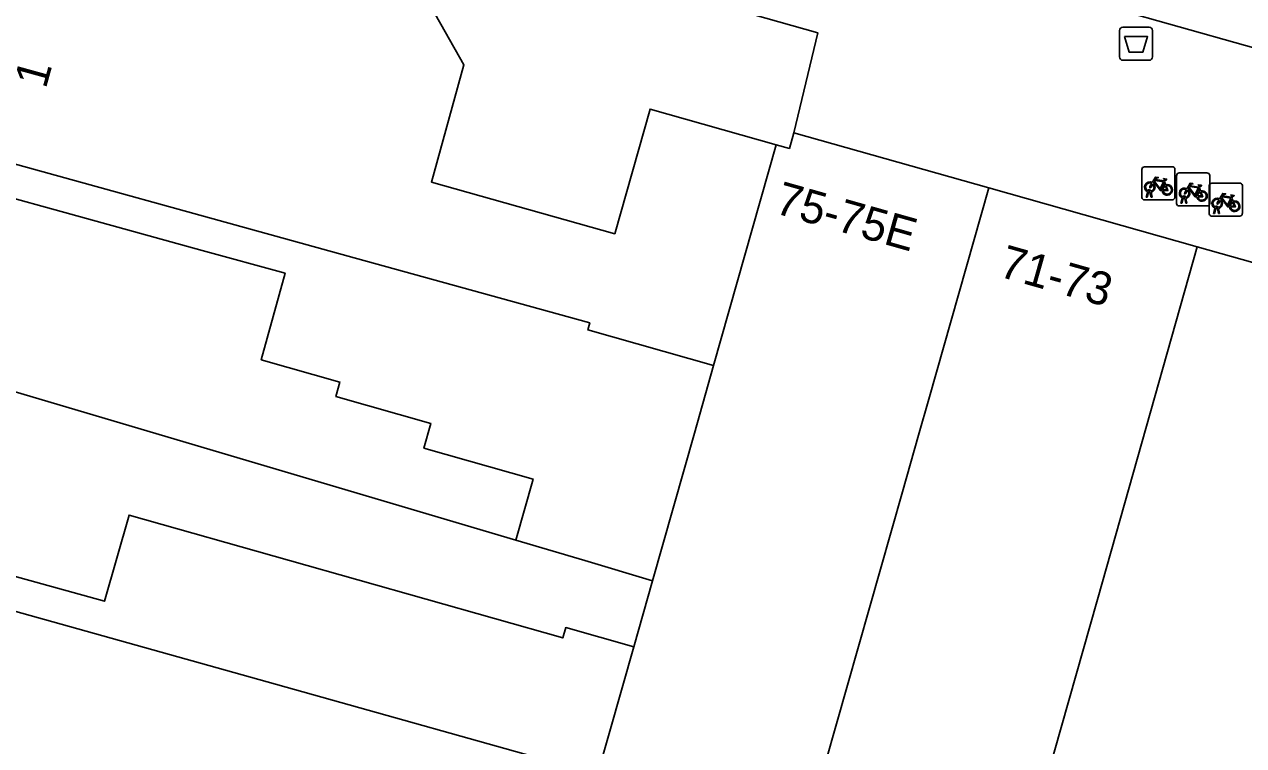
# Model space of a CAD drawing. Extents: x 158086 to 159499, y 382904 to 383981.
# Drawn here: x 158729.8 to 158766.64, y 383287.22 to 383309.02 of the extents above; entities that cross this region are included whole.
import ezdxf

# ---------------------------------------------------------------- set-up
doc = ezdxf.new("R2010")
doc.units = 0
for name, color, linetype in [('IMGEO_Afvalbak', 7, 'Continuous'), ('IMGEO_Erf', 7, 'Continuous'), ('IMGEO_Fietsenrek', 7, 'Continuous'), ('IMGEO_Pand', 7, 'Continuous'), ('IMGEO_Pand_nummerreeks', 7, 'Continuous'), ('IMGEO_Parkeervlak_open', 7, 'Continuous'), ('IMGEO_Voetpad_open', 7, 'Continuous')]:
    doc.layers.add(name, color=color, linetype=linetype)

msp = doc.modelspace()

# ---------------------------------------------------------------- linework, layer by layer
at = {"layer": 'IMGEO_Afvalbak'}
for p, q in [((158762.893, 383308.038), (158762.893, 383308.838)), ((158762.893, 383308.838), (158762.893, 383308.038)), ((158762.993, 383308.938), (158763.783, 383308.938)), ((158763.783, 383308.938), (158762.993, 383308.938)), ((158763.883, 383308.838), (158763.883, 383308.038)), ((158763.883, 383308.038), (158763.883, 383308.838)), ((158763.783, 383307.938), (158762.993, 383307.938)), ((158762.993, 383307.938), (158763.783, 383307.938))]:
    msp.add_line(p, q, dxfattribs=at)
msp.add_lwpolyline([(158763.036, 383308.652), (158763.74, 383308.652), (158763.591, 383308.182), (158763.185, 383308.182), (158763.036, 383308.652)], dxfattribs=at)
for centre, start, end in [((158762.993, 383308.838), 90, 180), ((158762.993, 383308.838), 90, 180), ((158763.783, 383308.838), 0, 90), ((158763.783, 383308.838), 360, 90), ((158762.993, 383308.038), 180, 270), ((158762.993, 383308.038), 180, 270), ((158763.783, 383308.038), 270, 0), ((158763.783, 383308.038), 270, 0)]:
    msp.add_arc(centre, 0.1, start, end, dxfattribs=at)
at = {"layer": 'IMGEO_Erf'}
for points in [[(158750.621, 383298.706), (158746.826, 383299.786), (158746.884, 383299.995), (158740.051, 383301.883), (158726.638, 383305.589), (158726.38, 383304.619), (158731.2, 383303.287), (158735.174, 383302.189), (158737.677, 383301.497), (158736.955, 383298.883), (158739.334, 383298.209), (158739.21, 383297.772), (158742.082, 383296.958), (158741.87, 383296.21), (158745.171, 383295.274), (158744.648, 383293.427), (158746.73, 383292.809), (158748.777, 383292.201), (158750.043, 383296.667)], [(158723.419, 383294.014), (158723.139, 383293.069), (158727.954, 383291.719), (158737.135, 383289.145), (158747.117, 383286.346), (158748.21, 383290.202), (158746.156, 383290.784), (158746.068, 383290.474), (158737.806, 383292.815), (158732.961, 383294.188), (158732.222, 383291.582), (158728.239, 383292.682)]]:
    msp.add_lwpolyline(points, close=True, dxfattribs=at)
at = {"layer": 'IMGEO_Fietsenrek'}
for p, q in [((158763.565, 383303.793), (158763.565, 383304.634)), ((158763.565, 383304.634), (158763.565, 383303.793)), ((158763.64, 383304.718), (158764.481, 383304.718)), ((158764.481, 383304.718), (158763.64, 383304.718)), ((158764.565, 383304.643), (158764.565, 383303.802)), ((158764.565, 383303.802), (158764.565, 383304.643)), ((158764.252, 383304.267), (158764.288, 383304.172)), ((158764.616, 383303.607), (158764.616, 383304.448)), ((158764.616, 383304.448), (158764.616, 383303.607)), ((158764.691, 383304.532), (158765.532, 383304.532)), ((158765.532, 383304.532), (158764.691, 383304.532)), ((158765.616, 383304.457), (158765.616, 383303.616)), ((158765.616, 383303.616), (158765.616, 383304.457)), ((158763.692, 383303.802), (158763.731, 383303.962)), ((158763.761, 383303.95), (158763.726, 383303.802)), ((158763.803, 383303.974), (158763.802, 383303.978)), ((158763.844, 383303.802), (158763.81, 383303.944)), ((158763.834, 383303.985), (158763.835, 383303.978)), ((158763.842, 383303.948), (158763.877, 383303.802)), ((158765.303, 383304.081), (158765.339, 383303.986)), ((158765.601, 383303.299), (158765.601, 383304.14)), ((158765.601, 383304.14), (158765.601, 383303.299)), ((158765.676, 383304.224), (158766.517, 383304.224)), ((158766.517, 383304.224), (158765.676, 383304.224)), ((158766.601, 383304.149), (158766.601, 383303.308)), ((158766.601, 383303.308), (158766.601, 383304.149)), ((158764.49, 383303.718), (158763.649, 383303.718)), ((158763.649, 383303.718), (158764.49, 383303.718)), ((158763.726, 383303.802), (158763.692, 383303.802)), ((158763.877, 383303.802), (158763.844, 383303.802)), ((158765.541, 383303.532), (158764.7, 383303.532)), ((158764.7, 383303.532), (158765.541, 383303.532)), ((158764.743, 383303.616), (158764.782, 383303.776)), ((158764.777, 383303.616), (158764.743, 383303.616)), ((158764.812, 383303.764), (158764.777, 383303.616)), ((158764.854, 383303.788), (158764.853, 383303.792)), ((158764.895, 383303.616), (158764.861, 383303.758)), ((158764.885, 383303.799), (158764.886, 383303.792)), ((158764.893, 383303.762), (158764.928, 383303.616)), ((158764.928, 383303.616), (158764.895, 383303.616)), ((158766.288, 383303.773), (158766.324, 383303.678)), ((158766.526, 383303.224), (158765.685, 383303.224)), ((158765.685, 383303.224), (158766.526, 383303.224)), ((158765.728, 383303.308), (158765.767, 383303.468)), ((158765.762, 383303.308), (158765.728, 383303.308)), ((158765.797, 383303.456), (158765.762, 383303.308)), ((158765.839, 383303.48), (158765.838, 383303.484)), ((158765.88, 383303.308), (158765.846, 383303.45)), ((158765.87, 383303.491), (158765.871, 383303.484)), ((158765.878, 383303.454), (158765.913, 383303.308)), ((158765.913, 383303.308), (158765.88, 383303.308))]:
    msp.add_line(p, q, dxfattribs=at)
for points in [[(158763.878, 383304.244), (158763.973, 383304.408), (158764.059, 383304.394), (158764.061, 383304.385), (158764.005, 383304.374), (158763.978, 383304.329), (158764.234, 383304.288)], [(158764.174, 383304), (158764.124, 383304), (158763.933, 383304.251), (158763.914, 383304.219)], [(158764.221, 383304.263), (158763.964, 383304.304), (158763.947, 383304.275), (158764.114, 383304.055), (158764.221, 383304.263)], [(158764.269, 383304.165), (158764.239, 383304.242), (158764.13, 383304.024), (158764.173, 383304.024)], [(158764.234, 383304.288), (158764.259, 383304.337), (158764.253, 383304.341), (158764.23, 383304.345), (158764.218, 383304.352), (158764.217, 383304.355), (158764.219, 383304.36), (158764.314, 383304.345), (158764.316, 383304.335), (158764.306, 383304.322), (158764.294, 383304.316), (158764.28, 383304.322), (158764.252, 383304.267)], [(158763.899, 383304.192), (158763.847, 383304.102), (158763.807, 383304.077), (158763.808, 383304.124), (158763.863, 383304.218)], [(158764.203, 383304.024), (158764.323, 383304.023), (158764.279, 383304.137)], [(158764.299, 383304.144), (158764.354, 383303.999), (158764.204, 383303.999)], [(158764.95, 383304.006), (158764.898, 383303.916), (158764.858, 383303.891), (158764.859, 383303.938), (158764.914, 383304.032)], [(158764.929, 383304.058), (158765.024, 383304.222), (158765.11, 383304.208), (158765.112, 383304.199), (158765.056, 383304.188), (158765.029, 383304.143), (158765.285, 383304.102)], [(158765.225, 383303.814), (158765.175, 383303.814), (158764.984, 383304.065), (158764.965, 383304.033)], [(158765.272, 383304.077), (158765.015, 383304.118), (158764.998, 383304.089), (158765.165, 383303.869), (158765.272, 383304.077)], [(158765.32, 383303.979), (158765.29, 383304.056), (158765.181, 383303.838), (158765.224, 383303.838)], [(158765.254, 383303.838), (158765.374, 383303.837), (158765.33, 383303.951)], [(158765.35, 383303.958), (158765.405, 383303.813), (158765.255, 383303.813)], [(158765.285, 383304.102), (158765.31, 383304.151), (158765.304, 383304.155), (158765.281, 383304.159), (158765.269, 383304.166), (158765.268, 383304.169), (158765.27, 383304.174), (158765.365, 383304.159), (158765.367, 383304.149), (158765.357, 383304.136), (158765.345, 383304.13), (158765.331, 383304.136), (158765.303, 383304.081)], [(158765.914, 383303.75), (158766.009, 383303.914), (158766.095, 383303.9), (158766.097, 383303.891), (158766.041, 383303.88), (158766.014, 383303.835), (158766.27, 383303.794)], [(158765.935, 383303.698), (158765.883, 383303.608), (158765.843, 383303.583), (158765.844, 383303.63), (158765.899, 383303.724)], [(158766.21, 383303.506), (158766.16, 383303.506), (158765.969, 383303.757), (158765.95, 383303.725)], [(158766.257, 383303.769), (158766, 383303.81), (158765.983, 383303.781), (158766.15, 383303.561), (158766.257, 383303.769)], [(158766.305, 383303.671), (158766.275, 383303.748), (158766.166, 383303.53), (158766.209, 383303.53)], [(158766.239, 383303.53), (158766.359, 383303.529), (158766.315, 383303.643)], [(158766.335, 383303.65), (158766.39, 383303.505), (158766.24, 383303.505)], [(158766.27, 383303.794), (158766.295, 383303.843), (158766.289, 383303.847), (158766.266, 383303.851), (158766.254, 383303.858), (158766.253, 383303.861), (158766.255, 383303.866), (158766.35, 383303.851), (158766.352, 383303.841), (158766.342, 383303.828), (158766.33, 383303.822), (158766.316, 383303.828), (158766.288, 383303.773)]]:
    msp.add_lwpolyline(points, dxfattribs=at)
for centre, radius, start, end in [((158763.643, 383304.64), 0.0779, 92.4484, 184.2845), ((158763.643, 383304.64), 0.0779, 92.4484, 184.2845), ((158764.487, 383304.64), 0.0779, 2.4484, 94.2845), ((158764.487, 383304.64), 0.0779, 2.4484, 94.2845), ((158763.805, 383304.103), 0.159, 62.6766, 242.1369), ((158764.694, 383304.454), 0.0779, 92.4484, 184.2845), ((158764.694, 383304.454), 0.0779, 92.4484, 184.2845), ((158765.538, 383304.454), 0.0779, 2.4484, 94.2845), ((158765.538, 383304.454), 0.0779, 2.4484, 94.2845), ((158763.805, 383304.103), 0.129, 63.3192, 238.903), ((158763.785, 383303.974), 0.0499, 12.8025, 158.6934), ((158763.805, 383304.103), 0.159, 253.9967, 271.7867), ((158763.785, 383303.974), 0.0174, 12.8025, 163.4502), ((158763.805, 383304.103), 0.129, 253.415, 269.0204), ((158763.805, 383304.103), 0.129, 283.6043, 43.4302), ((158763.805, 383304.103), 0.159, 283.5766, 46.6042), ((158764.332, 383304.019), 0.159, 113.3408, 178.3217), ((158764.332, 383304.019), 0.159, 187.0065, 105.7708), ((158764.332, 383304.019), 0.129, 113.923, 177.9556), ((158764.332, 383304.019), 0.129, 188.6715, 104.5883), ((158764.856, 383303.917), 0.159, 62.6766, 242.1369), ((158764.856, 383303.917), 0.129, 63.3192, 238.903), ((158764.856, 383303.917), 0.129, 283.6043, 43.4302), ((158764.856, 383303.917), 0.159, 283.5766, 46.6042), ((158765.383, 383303.833), 0.159, 113.3408, 178.3217), ((158765.383, 383303.833), 0.159, 187.0065, 105.7708), ((158765.383, 383303.833), 0.129, 113.923, 177.9556), ((158765.383, 383303.833), 0.129, 188.6715, 104.5883), ((158765.679, 383304.146), 0.0779, 92.4484, 184.2845), ((158765.679, 383304.146), 0.0779, 92.4484, 184.2845), ((158766.523, 383304.146), 0.0779, 2.4484, 94.2845), ((158766.523, 383304.146), 0.0779, 2.4484, 94.2845), ((158763.643, 383303.796), 0.0779, 182.4484, 274.2845), ((158763.643, 383303.796), 0.0779, 182.4484, 274.2845), ((158764.487, 383303.796), 0.0779, 272.4484, 4.2845), ((158764.487, 383303.796), 0.0779, 272.4484, 4.2845), ((158764.694, 383303.61), 0.0779, 182.4484, 274.2845), ((158764.694, 383303.61), 0.0779, 182.4484, 274.2845), ((158764.836, 383303.788), 0.0499, 12.8025, 158.6934), ((158764.856, 383303.917), 0.159, 253.9967, 271.7867), ((158764.836, 383303.788), 0.0174, 12.8025, 163.4502), ((158764.856, 383303.917), 0.129, 253.415, 269.0204), ((158765.538, 383303.61), 0.0779, 272.4484, 4.2845), ((158765.538, 383303.61), 0.0779, 272.4484, 4.2845), ((158765.841, 383303.609), 0.159, 62.6766, 242.1369), ((158765.841, 383303.609), 0.129, 63.3192, 238.903), ((158765.821, 383303.48), 0.0499, 12.8025, 158.6934), ((158765.841, 383303.609), 0.129, 283.6043, 43.4302), ((158765.841, 383303.609), 0.159, 283.5766, 46.6042), ((158766.368, 383303.525), 0.159, 113.3408, 178.3217), ((158766.368, 383303.525), 0.159, 187.0065, 105.7708), ((158766.368, 383303.525), 0.129, 113.923, 177.9556), ((158766.368, 383303.525), 0.129, 188.6715, 104.5883), ((158765.679, 383303.302), 0.0779, 182.4484, 274.2845), ((158765.679, 383303.302), 0.0779, 182.4484, 274.2845), ((158765.841, 383303.609), 0.159, 253.9967, 271.7867), ((158765.821, 383303.48), 0.0174, 12.8025, 163.4502), ((158765.841, 383303.609), 0.129, 253.415, 269.0204), ((158766.523, 383303.302), 0.0779, 272.4484, 4.2845), ((158766.523, 383303.302), 0.0779, 272.4484, 4.2845)]:
    msp.add_arc(centre, radius, start, end, dxfattribs=at)
at = {"layer": 'IMGEO_Pand'}
for points in [[(158734.063, 383310.168), (158729.552, 383311.413), (158728.013, 383310.572), (158726.638, 383305.589), (158740.051, 383301.883), (158746.884, 383299.995), (158746.826, 383299.786), (158750.621, 383298.706), (158752.515, 383305.385), (158748.706, 383306.463), (158747.639, 383302.691), (158742.1, 383304.249), (158743.079, 383307.796), (158742.083, 383309.564), (158738.149, 383310.65), (158736.503, 383309.495), (158734.326, 383310.095)], [(158756.328, 383294.885), (158756.815, 383296.607), (158757.123, 383297.693), (158758.936, 383304.084), (158753.051, 383305.749), (158752.916, 383305.271), (158752.515, 383305.385), (158750.621, 383298.706), (158750.043, 383296.667), (158748.777, 383292.201), (158748.21, 383290.202), (158747.117, 383286.346), (158745.223, 383279.663), (158745.391, 383279.615), (158745.532, 383279.575), (158748.385, 383278.764), (158751.259, 383277.947), (158751.502, 383277.878), (158751.64, 383278.365), (158751.727, 383278.671), (158752.016, 383279.689)], [(158726.38, 383304.619), (158724.891, 383299.284), (158744.648, 383293.427), (158745.171, 383295.274), (158741.87, 383296.21), (158742.082, 383296.958), (158739.21, 383297.772), (158739.334, 383298.209), (158736.955, 383298.883), (158737.677, 383301.497), (158735.174, 383302.189), (158731.2, 383303.287)], [(158765.24, 383302.3), (158758.936, 383304.084), (158757.123, 383297.693), (158756.815, 383296.607), (158756.328, 383294.885), (158752.016, 383279.689), (158751.727, 383278.671), (158751.64, 383278.365), (158756.857, 383276.876), (158757.951, 383276.564), (158758.04, 383276.878), (158758.351, 383277.976), (158758.97, 383280.162), (158762.22, 383291.637), (158763.046, 383294.553)], [(158771.394, 383300.559), (158765.24, 383302.3), (158763.046, 383294.553), (158762.22, 383291.637), (158758.97, 383280.162), (158765.125, 383278.419), (158768.375, 383289.897)], [(158724.891, 383299.284), (158723.419, 383294.014), (158728.239, 383292.682), (158732.222, 383291.582), (158732.961, 383294.188), (158737.806, 383292.815), (158746.068, 383290.474), (158746.156, 383290.784), (158748.21, 383290.202), (158748.777, 383292.201), (158746.73, 383292.809), (158744.648, 383293.427)], [(158747.117, 383286.346), (158737.135, 383289.145), (158727.954, 383291.719), (158723.139, 383293.069), (158720.882, 383285.022), (158729.99, 383282.438), (158730.021, 383282.546), (158734.867, 383281.172), (158742.063, 383279.133), (158745.03, 383278.292), (158745.391, 383279.615), (158745.223, 383279.663)]]:
    msp.add_lwpolyline(points, close=True, dxfattribs=at)
at = {"layer": 'IMGEO_Parkeervlak_open'}
msp.add_lwpolyline([(158740.08, 383315.894), (158750.747, 383312.925), (158754.382, 383311.869), (158760.681, 383310.087), (158772.705, 383306.69), (158776.574, 383305.607)], dxfattribs=at)
at = {"layer": 'IMGEO_Voetpad_open'}
for points in [[(158776.574, 383305.607), (158772.705, 383306.69), (158760.681, 383310.087), (158754.382, 383311.869), (158754.232, 383311.354), (158750.618, 383312.408), (158750.747, 383312.925), (158740.08, 383315.894)], [(158729.552, 383311.413), (158734.063, 383310.168), (158735.098, 383314.047), (158753.77, 383308.767), (158753.051, 383305.749), (158758.936, 383304.084), (158765.24, 383302.3), (158771.394, 383300.559), (158777.811, 383298.744), (158780.697, 383297.927), (158787.49, 383296.004), (158790.372, 383295.088), (158799.862, 383292.403)]]:
    msp.add_lwpolyline(points, dxfattribs=at)
msp.add_lwpolyline([(158734.326, 383310.095), (158736.503, 383309.495), (158738.149, 383310.65), (158742.083, 383309.564), (158743.079, 383307.796), (158742.1, 383304.249), (158747.639, 383302.691), (158748.706, 383306.463), (158752.515, 383305.385), (158752.916, 383305.271), (158753.051, 383305.749), (158753.77, 383308.767), (158735.098, 383314.047), (158734.063, 383310.168)], close=True, dxfattribs=at)

# ---------------------------------------------------------------- texts
at = {"layer": 'IMGEO_Pand_nummerreeks'}
for s, rotation, p in [('1', 74.5738, (158730.444, 383307.053)), ('75-75E', 344.2036, (158752.434, 383303.325)), ('71-73', 344.1978, (158759.206, 383301.409))]:
    msp.add_text(s, height=1, rotation=rotation, dxfattribs=at).set_placement(p)

doc.saveas('drawing.dxf')
